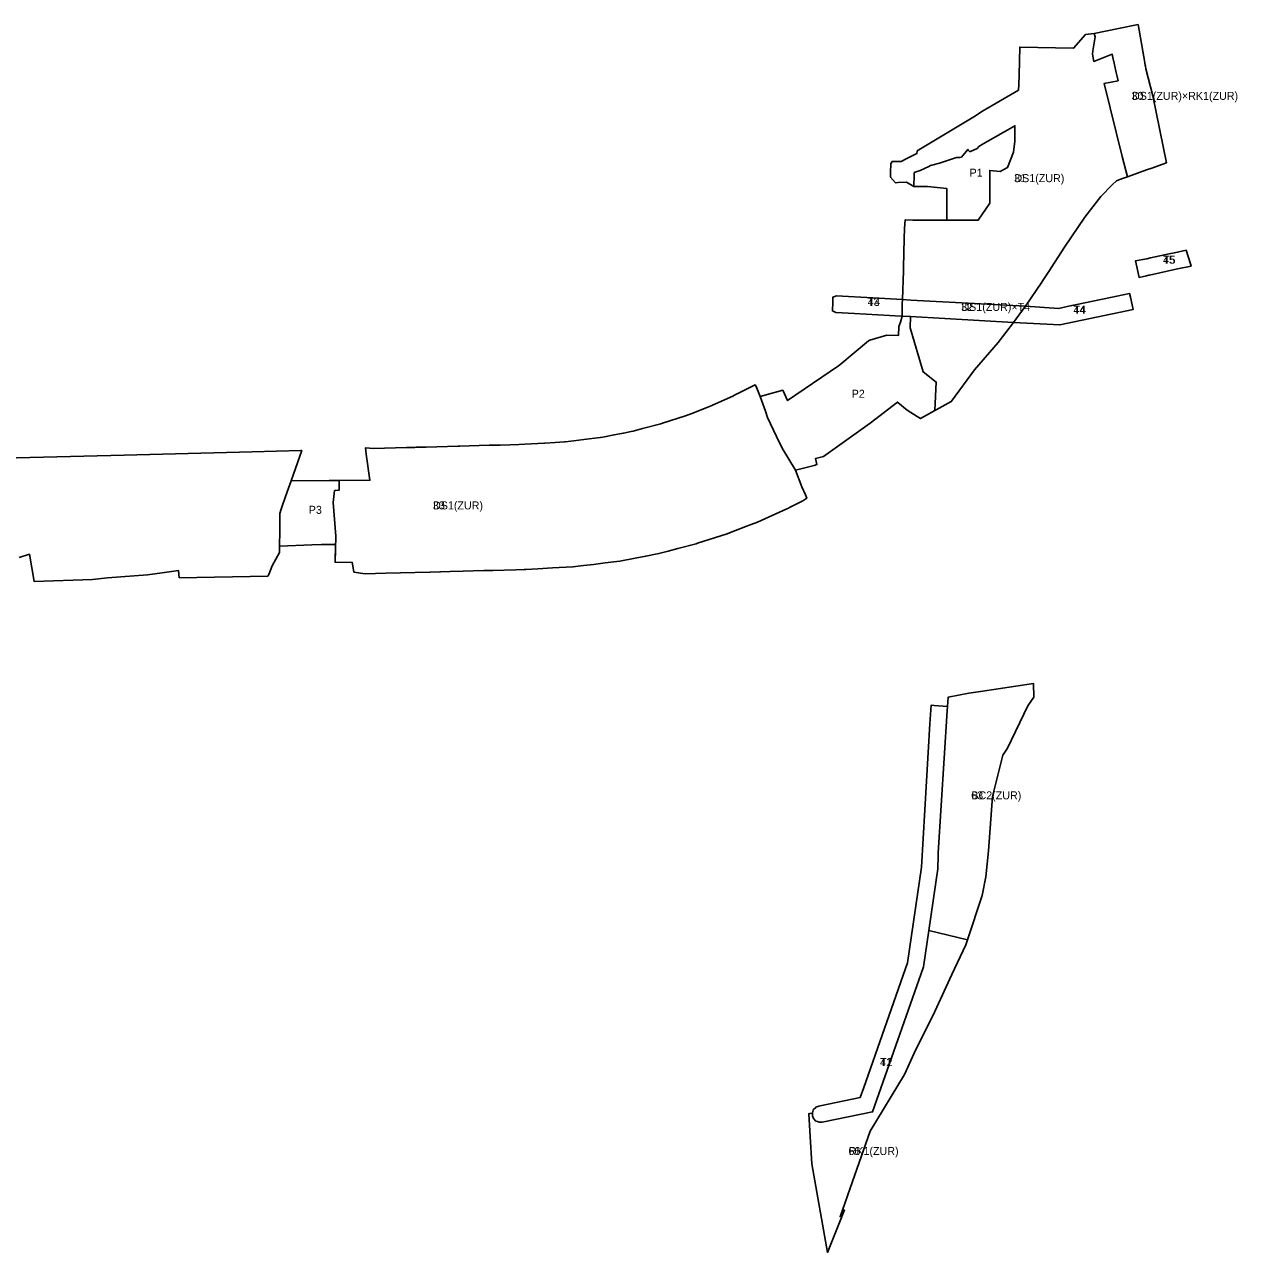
# Model space of a CAD drawing. Extents: x -501732 to -497651, y -1141409 to -1138069.
# Drawn here: x -498863 to -497651, y -1141409 to -1140182 of the extents above; entities that cross this region are included whole.
import ezdxf

# ---------------------------------------------------------------- set-up
doc = ezdxf.new("R2010")
doc.units = 0
for name, color, linetype in [('45', 7, 'Continuous'), ('51', 7, 'Continuous'), ('57', 7, 'Continuous'), ('59', 7, 'Continuous'), ('61', 7, 'Continuous'), ('62', 7, 'Continuous')]:
    doc.layers.add(name, color=color, linetype=linetype)

msp = doc.modelspace()

# ---------------------------------------------------------------- linework, layer by layer
at = {"layer": '45'}
for points in [[(-497873.51, -1140298.79), (-497874.77, -1140309.65), (-497880.89, -1140325.03), (-497888.02, -1140329.02), (-497898.51, -1140327.82), (-497898.53, -1140332.95), (-497898.6, -1140360.76), (-497910.06, -1140377.52), (-497914.148, -1140377.525), (-497941.564, -1140377.56), (-497941.57, -1140368.44), (-497941.52, -1140345.9), (-497960.94, -1140344.13), (-497972.87, -1140344.1), (-497974.54, -1140344.08), (-497974.21, -1140332.78), (-497974.13, -1140330.03), (-497967.99, -1140327.91), (-497959.454, -1140323.965), (-497957.69, -1140323.15), (-497956.48, -1140322.59), (-497948.98, -1140320.67), (-497931.93, -1140315.11), (-497928.49, -1140314.89), (-497926.91, -1140314.69), (-497920.36, -1140306.97), (-497920.1, -1140307.6), (-497918.69, -1140308.92), (-497917.76, -1140308.87), (-497911.33, -1140306.13), (-497909.39, -1140303.84), (-497905.09, -1140301.37), (-497882.9, -1140288.64), (-497873.46, -1140283.27), (-497873.49, -1140294.66)], [(-497977.812, -1140473.956), (-497978.1, -1140485.38), (-497965, -1140529.36), (-497952.03, -1140539.4), (-497953.325, -1140567.764), (-497967.87, -1140575.85), (-497971.23, -1140573.7), (-497981.02, -1140567.46), (-497990.31, -1140559.8), (-497990.749, -1140559.512), (-498018.24, -1140580.59), (-498064.77, -1140613.68), (-498072.91, -1140615.93), (-498071.35, -1140621.9), (-498074.25, -1140622.66), (-498092.81, -1140627.56), (-498106.12, -1140605.53), (-498111.793, -1140593.803), (-498120.9, -1140574.98), (-498122.87, -1140568.4), (-498128.1, -1140553.78), (-498105.46, -1140547.59), (-498100.702, -1140557.857), (-498049.646, -1140523.081), (-498048.385, -1140522.079), (-498019.752, -1140498.076), (-498018.382, -1140497.674), (-498001.33, -1140492.67), (-497989.83, -1140492.96), (-497989.6, -1140483.98), (-497987.8, -1140479.4), (-497986.174, -1140473.486)], [(-498596.956, -1140637.987), (-498558.761, -1140637.77), (-498549.008, -1140637.715), (-498549, -1140647.5), (-498553.57, -1140647.82), (-498554.94, -1140659.83), (-498552.29, -1140693.37), (-498553.06, -1140719.57), (-498552.643, -1140701.808), (-498559.063, -1140701.72), (-498566.41, -1140701.62), (-498576.28, -1140701.95), (-498608.546, -1140703.543), (-498608.24, -1140688.18), (-498608.2, -1140670.84), (-498606.99, -1140666.48), (-498605.42, -1140662.56), (-498600.801, -1140649.149)]]:
    msp.add_lwpolyline(points, close=True, dxfattribs=at)
at = {"layer": '51'}
for points in [[(-497750.361, -1140182.123), (-497744.65, -1140214.23), (-497744.34, -1140215.94), (-497743.12, -1140222.81), (-497742.97, -1140223.61), (-497742.46, -1140226.49), (-497735.58, -1140253.46), (-497722.038, -1140320.293), (-497733.802, -1140324.516), (-497736.638, -1140325.534), (-497741.761, -1140327.373), (-497757.255, -1140332.936), (-497760.746, -1140334.19), (-497766.22, -1140314.06), (-497784.27, -1140241.09), (-497770.35, -1140238.29), (-497771.3, -1140234.04), (-497772.19, -1140230.04), (-497773.87, -1140222.54), (-497774.27, -1140220.73), (-497775.52, -1140215.16), (-497776.29, -1140211.71), (-497794.66, -1140218.96), (-497796.02, -1140211.8), (-497795.48, -1140208.51), (-497793.18, -1140194.54), (-497794.171, -1140191.113), (-497769.85, -1140186.122)], [(-497793.18, -1140194.54), (-497795.48, -1140208.51), (-497796.02, -1140211.8), (-497794.66, -1140218.96), (-497776.29, -1140211.71), (-497775.52, -1140215.16), (-497774.27, -1140220.73), (-497773.87, -1140222.54), (-497772.19, -1140230.04), (-497771.3, -1140234.04), (-497770.35, -1140238.29), (-497784.27, -1140241.09), (-497766.22, -1140314.06), (-497760.746, -1140334.19), (-497765.849, -1140336.021), (-497768.534, -1140336.985), (-497771.924, -1140338.202), (-497776.305, -1140342.26), (-497787.404, -1140354.097), (-497803.679, -1140374.661), (-497823.893, -1140404.582), (-497840.21, -1140429.769), (-497845.516, -1140437.96), (-497846.62, -1140439.663), (-497862.96, -1140463.494), (-497977.396, -1140457.425), (-497985.937, -1140456.951), (-497984.944, -1140428.367), (-497984.83, -1140425.08), (-497984.067, -1140395.824), (-497983.81, -1140385.99), (-497983.185, -1140377.342), (-497975.381, -1140377.464), (-497957.21, -1140377.58), (-497941.564, -1140377.56), (-497941.57, -1140368.44), (-497941.52, -1140345.9), (-497960.94, -1140344.13), (-497972.87, -1140344.1), (-497974.54, -1140344.08), (-497981.91, -1140339.55), (-497990.299, -1140340.023), (-497992.965, -1140340.174), (-497997.64, -1140334.52), (-497997.649, -1140330.097), (-497997.617, -1140321.437), (-497997.053, -1140320.376), (-497996.942, -1140320.168), (-497996.24, -1140318.85), (-497987.3, -1140318.88), (-497981.4, -1140315.98), (-497971.33, -1140311.03), (-497971.26, -1140308.34), (-497912.788, -1140273.253), (-497906.46, -1140269.12), (-497869.75, -1140247.65), (-497869.596, -1140242.152), (-497869.32, -1140232.34), (-497868.54, -1140204.71), (-497814.724, -1140205.764), (-497803.04, -1140192.08), (-497794.171, -1140191.113)], [(-497742.025, -1140433.137), (-497749.305, -1140434.783), (-497752.954, -1140418.426), (-497745.487, -1140417.036), (-497741.556, -1140416.179), (-497738.052, -1140415.414), (-497719.331, -1140411.328), (-497714.01, -1140410.166), (-497702.315, -1140407.614), (-497697.93, -1140421.1), (-497697.403, -1140423.438), (-497710.808, -1140426.361), (-497738.975, -1140432.504), (-497739.599, -1140432.64)], [(-497757.956, -1140454.716), (-497755.151, -1140466.802), (-497828.392, -1140482.359), (-497841.639, -1140481.614), (-497874.808, -1140479.748), (-497863.221, -1140463.874), (-497862.96, -1140463.494), (-497829.666, -1140465.761), (-497821.285, -1140463.981), (-497777.943, -1140454.775), (-497758.85, -1140450.865)], [(-497985.937, -1140456.951), (-497986.07, -1140460.79), (-497986.174, -1140473.486), (-497987.181, -1140473.429), (-498033.913, -1140470.801), (-498052.607, -1140469.75), (-498055.788, -1140468.341), (-498055.53, -1140459.47), (-498055.484, -1140457.899), (-498055.384, -1140454.516), (-498051.68, -1140453.276), (-498015.461, -1140455.312)], [(-497863.221, -1140463.874), (-497874.808, -1140479.748), (-497977.812, -1140473.956), (-497986.174, -1140473.486), (-497986.07, -1140460.79), (-497985.937, -1140456.951), (-497977.396, -1140457.425), (-497862.96, -1140463.494)], [(-497940.79, -1140863.814), (-497941.059, -1140868.085), (-497950, -1141010), (-497950.085, -1141012.957), (-497950.453, -1141025.823), (-497959.442, -1141087.571), (-497964.714, -1141123.789), (-497965.056, -1141124.761), (-498015.675, -1141268.789), (-498064.477, -1141278.806), (-498066.144, -1141279.148), (-498069.236, -1141279.192), (-498070.925, -1141278.52), (-498072.345, -1141277.955), (-498074.707, -1141275.584), (-498075.885, -1141272.726), (-498075.895, -1141272.009), (-498075.921, -1141270.104), (-498075.928, -1141269.635), (-498074.954, -1141267.186), (-498074.691, -1141266.526), (-498072.598, -1141264.44), (-498072.32, -1141264.164), (-498069.462, -1141262.986), (-498068.179, -1141262.723), (-498028.144, -1141254.504), (-498024.601, -1141244.424), (-497980.812, -1141119.828), (-497966.901, -1141024.267), (-497958.345, -1140881.029), (-497957.238, -1140862.504), (-497954.3, -1140862.62)]]:
    msp.add_lwpolyline(points, close=True, dxfattribs=at)
msp.add_lwpolyline([(-498911.97, -1140616.22), (-498763.779, -1140612.414), (-498635.836, -1140608.996), (-498587.232, -1140607.698), (-498586.309, -1140607.658), (-498594.68, -1140631.38), (-498596.956, -1140637.987), (-498558.761, -1140637.77), (-498549.008, -1140637.715), (-498518.24, -1140637.54), (-498521.824, -1140611.416), (-498522.66, -1140605.32), (-498514.662, -1140605.76), (-498481.482, -1140604.874), (-498479.827, -1140604.83), (-498473.333, -1140604.656), (-498471.913, -1140604.618), (-498462.065, -1140604.355), (-498440.64, -1140603.783), (-498430.138, -1140603.502), (-498428.221, -1140603.451), (-498419.006, -1140603.196), (-498398.992, -1140602.641), (-498387.928, -1140602.335), (-498377.939, -1140602.058), (-498369.099, -1140601.813), (-498363.353, -1140601.491), (-498343.694, -1140600.388), (-498343.303, -1140600.366), (-498333.112, -1140599.794), (-498323.736, -1140599.268), (-498323.104, -1140599.19), (-498314.182, -1140598.086), (-498304.366, -1140596.872), (-498287.957, -1140594.843), (-498285.35, -1140594.337), (-498274.137, -1140592.159), (-498264.802, -1140590.346), (-498257.129, -1140588.856), (-498255.131, -1140588.333), (-498245.571, -1140585.832), (-498227.312, -1140581.055), (-498225.57, -1140580.489), (-498202.84, -1140573.11), (-498196.526, -1140570.684), (-498180.452, -1140564.508), (-498178.766, -1140563.86), (-498155.285, -1140553.385), (-498151.261, -1140551.331), (-498150.408, -1140550.895), (-498137.212, -1140544.157), (-498133.079, -1140542.247), (-498132.18, -1140543.96), (-498128.1, -1140553.78), (-498105.46, -1140547.59), (-498100.702, -1140557.857), (-498049.646, -1140523.081), (-498048.385, -1140522.079), (-498019.752, -1140498.076), (-498018.382, -1140497.674), (-498001.33, -1140492.67), (-497989.83, -1140492.96), (-497989.6, -1140483.98), (-497987.8, -1140479.4), (-497986.174, -1140473.486), (-497977.812, -1140473.956), (-497874.808, -1140479.748), (-497890.3, -1140499.996), (-497913.717, -1140527.13), (-497936.936, -1140558.427), (-497936.83, -1140558.56), (-497936.62, -1140558.714), (-497937.22, -1140558.81), (-497967.87, -1140575.85), (-497971.23, -1140573.7), (-497981.02, -1140567.46), (-497990.31, -1140559.8), (-497990.749, -1140559.512), (-498018.24, -1140580.59), (-498064.77, -1140613.68), (-498072.91, -1140615.93), (-498071.35, -1140621.9), (-498074.25, -1140622.66), (-498092.81, -1140627.56), (-498086.34, -1140644.21), (-498082.67, -1140652.13), (-498081.436, -1140655.582), (-498085.369, -1140658.038), (-498098.651, -1140664.82), (-498099.854, -1140665.434), (-498101.363, -1140666.204), (-498130.852, -1140679.36), (-498140.654, -1140683.126), (-498158.761, -1140690.084), (-498161.095, -1140690.981), (-498190.601, -1140700.559), (-498192.164, -1140701.066), (-498210.389, -1140705.834), (-498219.943, -1140708.334), (-498229.365, -1140710.799), (-498231.078, -1140711.132), (-498242.417, -1140713.334), (-498252.872, -1140715.365), (-498268.347, -1140718.37), (-498274.437, -1140719.123), (-498283.056, -1140720.189), (-498294.735, -1140721.634), (-498304.746, -1140722.872), (-498312.551, -1140723.837), (-498315.16, -1140723.983), (-498315.351, -1140723.994), (-498335.52, -1140725.126), (-498335.576, -1140725.129), (-498350.18, -1140725.948), (-498362.193, -1140726.622), (-498363.866, -1140726.716), (-498372.437, -1140726.953), (-498395.246, -1140727.586), (-498404.381, -1140727.839), (-498415.103, -1140728.136), (-498424.822, -1140728.405), (-498438.021, -1140728.758), (-498447.686, -1140729.016), (-498448.223, -1140729.03), (-498457.932, -1140729.289), (-498458.141, -1140729.295), (-498502.393, -1140730.477), (-498522.815, -1140731.022), (-498534.089, -1140729.416), (-498535.16, -1140723.08), (-498535.79, -1140719.63), (-498553.06, -1140719.57), (-498552.643, -1140701.808), (-498559.063, -1140701.72), (-498566.41, -1140701.62), (-498576.28, -1140701.95), (-498608.546, -1140703.543), (-498608.67, -1140709.77), (-498616.02, -1140723.18), (-498619.06, -1140731.91), (-498620.29, -1140733.478), (-498708.816, -1140735.001), (-498709.65, -1140727.63), (-498725.72, -1140729.92), (-498740.49, -1140732.02), (-498780.63, -1140734.94), (-498795.52, -1140736.85), (-498853.837, -1140738.595), (-498858.59, -1140711.59), (-498868.78, -1140714.9)], dxfattribs=at)
at = {"layer": '57'}
for points in [[(-497750.361, -1140182.123), (-497744.65, -1140214.23), (-497744.34, -1140215.94), (-497743.12, -1140222.81), (-497742.97, -1140223.61), (-497742.46, -1140226.49), (-497735.58, -1140253.46), (-497722.038, -1140320.293), (-497733.802, -1140324.516), (-497736.638, -1140325.534), (-497741.761, -1140327.373), (-497757.255, -1140332.936), (-497760.746, -1140334.19), (-497766.22, -1140314.06), (-497784.27, -1140241.09), (-497770.35, -1140238.29), (-497771.3, -1140234.04), (-497772.19, -1140230.04), (-497773.87, -1140222.54), (-497774.27, -1140220.73), (-497775.52, -1140215.16), (-497776.29, -1140211.71), (-497794.66, -1140218.96), (-497796.02, -1140211.8), (-497795.48, -1140208.51), (-497793.18, -1140194.54), (-497794.171, -1140191.113), (-497769.85, -1140186.122)], [(-497906.09, -1141052.54), (-497920.923, -1141096.824), (-497959.442, -1141087.571), (-497950.453, -1141025.823), (-497950.085, -1141012.957), (-497950, -1141010), (-497941.059, -1140868.085), (-497940.79, -1140863.814), (-497940.12, -1140854.25), (-497919.46, -1140850.42), (-497907.84, -1140848.72), (-497854.86, -1140840.55), (-497854.48, -1140854.34), (-497860.49, -1140863.16), (-497880.69, -1140905.18), (-497885.67, -1140912.21), (-497895.94, -1140953.5), (-497899.9, -1141008.04), (-497902.6, -1141034.05)], [(-497920.923, -1141096.824), (-497922.56, -1141101.71), (-497936.6, -1141131.47), (-497953.58, -1141168.63), (-497974.01, -1141210.14), (-497983.96, -1141231.47), (-498018.11, -1141287.98), (-498035.73, -1141338.3), (-498048.14, -1141373.58), (-498043.93, -1141366.76), (-498048.79, -1141379.42), (-498060.66, -1141409.3), (-498076.29, -1141320.9), (-498078.06, -1141293.56), (-498079.54, -1141270.72), (-498078.55, -1141270.48), (-498075.921, -1141270.104), (-498075.895, -1141272.009), (-498075.885, -1141272.726), (-498074.707, -1141275.584), (-498072.345, -1141277.955), (-498070.925, -1141278.52), (-498069.236, -1141279.192), (-498066.144, -1141279.148), (-498064.477, -1141278.806), (-498015.675, -1141268.789), (-497965.056, -1141124.761), (-497964.714, -1141123.789), (-497959.442, -1141087.571)]]:
    msp.add_lwpolyline(points, close=True, dxfattribs=at)
at = {"layer": '59'}
msp.add_lwpolyline([(-498911.97, -1140616.22), (-498763.779, -1140612.414), (-498635.836, -1140608.996), (-498587.232, -1140607.698), (-498586.309, -1140607.658), (-498594.68, -1140631.38), (-498596.956, -1140637.987), (-498558.761, -1140637.77), (-498549.008, -1140637.715), (-498518.24, -1140637.54), (-498521.824, -1140611.416), (-498522.66, -1140605.32), (-498514.662, -1140605.76), (-498481.482, -1140604.874), (-498479.827, -1140604.83), (-498473.333, -1140604.656), (-498471.913, -1140604.618), (-498462.065, -1140604.355), (-498440.64, -1140603.783), (-498430.138, -1140603.502), (-498428.221, -1140603.451), (-498419.006, -1140603.196), (-498398.992, -1140602.641), (-498387.928, -1140602.335), (-498377.939, -1140602.058), (-498369.099, -1140601.813), (-498363.353, -1140601.491), (-498343.694, -1140600.388), (-498343.303, -1140600.366), (-498333.112, -1140599.794), (-498323.736, -1140599.268), (-498323.104, -1140599.19), (-498314.182, -1140598.086), (-498304.366, -1140596.872), (-498287.957, -1140594.843), (-498285.35, -1140594.337), (-498274.137, -1140592.159), (-498264.802, -1140590.346), (-498257.129, -1140588.856), (-498255.131, -1140588.333), (-498245.571, -1140585.832), (-498227.312, -1140581.055), (-498225.57, -1140580.489), (-498202.84, -1140573.11), (-498196.526, -1140570.684), (-498180.452, -1140564.508), (-498178.766, -1140563.86), (-498155.285, -1140553.385), (-498151.261, -1140551.331), (-498150.408, -1140550.895), (-498137.212, -1140544.157), (-498133.079, -1140542.247), (-498132.18, -1140543.96), (-498128.1, -1140553.78), (-498105.46, -1140547.59), (-498100.702, -1140557.857), (-498049.646, -1140523.081), (-498048.385, -1140522.079), (-498019.752, -1140498.076), (-498018.382, -1140497.674), (-498001.33, -1140492.67), (-497989.83, -1140492.96), (-497989.6, -1140483.98), (-497987.8, -1140479.4), (-497986.174, -1140473.486), (-497987.181, -1140473.429), (-498033.913, -1140470.801), (-498052.607, -1140469.75), (-498055.788, -1140468.341), (-498055.53, -1140459.47), (-498055.484, -1140457.899), (-498055.384, -1140454.516), (-498051.68, -1140453.276), (-498015.461, -1140455.312), (-497985.937, -1140456.951), (-497984.944, -1140428.367), (-497984.83, -1140425.08), (-497984.067, -1140395.824), (-497983.81, -1140385.99), (-497983.185, -1140377.342), (-497975.381, -1140377.464), (-497957.21, -1140377.58), (-497941.564, -1140377.56), (-497941.57, -1140368.44), (-497941.52, -1140345.9), (-497960.94, -1140344.13), (-497972.87, -1140344.1), (-497974.54, -1140344.08), (-497981.91, -1140339.55), (-497990.299, -1140340.023), (-497992.965, -1140340.174), (-497997.64, -1140334.52), (-497997.649, -1140330.097), (-497997.617, -1140321.437), (-497997.053, -1140320.376), (-497996.942, -1140320.168), (-497996.24, -1140318.85), (-497987.3, -1140318.88), (-497981.4, -1140315.98), (-497971.33, -1140311.03), (-497971.26, -1140308.34), (-497912.788, -1140273.253), (-497906.46, -1140269.12), (-497869.75, -1140247.65), (-497869.596, -1140242.152), (-497869.32, -1140232.34), (-497868.54, -1140204.71), (-497814.724, -1140205.764), (-497803.04, -1140192.08), (-497794.171, -1140191.113), (-497769.85, -1140186.122), (-497750.361, -1140182.123), (-497744.65, -1140214.23), (-497744.34, -1140215.94), (-497743.12, -1140222.81), (-497742.97, -1140223.61), (-497742.46, -1140226.49), (-497735.58, -1140253.46), (-497722.038, -1140320.293), (-497733.802, -1140324.516), (-497736.638, -1140325.534), (-497741.761, -1140327.373), (-497757.255, -1140332.936), (-497760.746, -1140334.19), (-497765.849, -1140336.021), (-497768.534, -1140336.985), (-497771.924, -1140338.202), (-497776.305, -1140342.26), (-497787.404, -1140354.097), (-497803.679, -1140374.661), (-497823.893, -1140404.582), (-497840.21, -1140429.769), (-497845.516, -1140437.96), (-497846.62, -1140439.663), (-497862.96, -1140463.494), (-497829.666, -1140465.761), (-497821.285, -1140463.981), (-497777.943, -1140454.775), (-497758.85, -1140450.865), (-497757.956, -1140454.716), (-497755.151, -1140466.802), (-497828.392, -1140482.359), (-497841.639, -1140481.614), (-497874.808, -1140479.748), (-497890.3, -1140499.996), (-497913.717, -1140527.13), (-497936.936, -1140558.427), (-497936.83, -1140558.56), (-497936.62, -1140558.714), (-497937.22, -1140558.81), (-497967.87, -1140575.85), (-497971.23, -1140573.7), (-497981.02, -1140567.46), (-497990.31, -1140559.8), (-497990.749, -1140559.512), (-498018.24, -1140580.59), (-498064.77, -1140613.68), (-498072.91, -1140615.93), (-498071.35, -1140621.9), (-498074.25, -1140622.66), (-498092.81, -1140627.56), (-498086.34, -1140644.21), (-498082.67, -1140652.13), (-498081.436, -1140655.582), (-498085.369, -1140658.038), (-498098.651, -1140664.82), (-498099.854, -1140665.434), (-498101.363, -1140666.204), (-498130.852, -1140679.36), (-498140.654, -1140683.126), (-498158.761, -1140690.084), (-498161.095, -1140690.981), (-498190.601, -1140700.559), (-498192.164, -1140701.066), (-498210.389, -1140705.834), (-498219.943, -1140708.334), (-498229.365, -1140710.799), (-498231.078, -1140711.132), (-498242.417, -1140713.334), (-498252.872, -1140715.365), (-498268.347, -1140718.37), (-498274.437, -1140719.123), (-498283.056, -1140720.189), (-498294.735, -1140721.634), (-498304.746, -1140722.872), (-498312.551, -1140723.837), (-498315.16, -1140723.983), (-498315.351, -1140723.994), (-498335.52, -1140725.126), (-498335.576, -1140725.129), (-498350.18, -1140725.948), (-498362.193, -1140726.622), (-498363.866, -1140726.716), (-498372.437, -1140726.953), (-498395.246, -1140727.586), (-498404.381, -1140727.839), (-498415.103, -1140728.136), (-498424.822, -1140728.405), (-498438.021, -1140728.758), (-498447.686, -1140729.016), (-498448.223, -1140729.03), (-498457.932, -1140729.289), (-498458.141, -1140729.295), (-498502.393, -1140730.477), (-498522.815, -1140731.022), (-498534.089, -1140729.416), (-498535.16, -1140723.08), (-498535.79, -1140719.63), (-498553.06, -1140719.57), (-498552.643, -1140701.808), (-498559.063, -1140701.72), (-498566.41, -1140701.62), (-498576.28, -1140701.95), (-498608.546, -1140703.543), (-498608.67, -1140709.77), (-498616.02, -1140723.18), (-498619.06, -1140731.91), (-498620.29, -1140733.478), (-498708.816, -1140735.001), (-498709.65, -1140727.63), (-498725.72, -1140729.92), (-498740.49, -1140732.02), (-498780.63, -1140734.94), (-498795.52, -1140736.85), (-498853.837, -1140738.595), (-498858.59, -1140711.59), (-498868.78, -1140714.9)], dxfattribs=at)
for points in [[(-497742.025, -1140433.137), (-497749.305, -1140434.783), (-497752.954, -1140418.426), (-497745.487, -1140417.036), (-497741.556, -1140416.179), (-497738.052, -1140415.414), (-497719.331, -1140411.328), (-497714.01, -1140410.166), (-497702.315, -1140407.614), (-497697.93, -1140421.1), (-497697.403, -1140423.438), (-497710.808, -1140426.361), (-497738.975, -1140432.504), (-497739.599, -1140432.64)], [(-497860.49, -1140863.16), (-497880.69, -1140905.18), (-497885.67, -1140912.21), (-497895.94, -1140953.5), (-497899.9, -1141008.04), (-497902.6, -1141034.05), (-497906.09, -1141052.54), (-497920.923, -1141096.824), (-497922.56, -1141101.71), (-497936.6, -1141131.47), (-497953.58, -1141168.63), (-497974.01, -1141210.14), (-497983.96, -1141231.47), (-498018.11, -1141287.98), (-498035.73, -1141338.3), (-498048.14, -1141373.58), (-498043.93, -1141366.76), (-498048.79, -1141379.42), (-498060.66, -1141409.3), (-498076.29, -1141320.9), (-498078.06, -1141293.56), (-498079.54, -1141270.72), (-498078.55, -1141270.48), (-498075.921, -1141270.104), (-498075.928, -1141269.635), (-498074.954, -1141267.186), (-498074.691, -1141266.526), (-498072.598, -1141264.44), (-498072.32, -1141264.164), (-498069.462, -1141262.986), (-498068.179, -1141262.723), (-498028.144, -1141254.504), (-498024.601, -1141244.424), (-497980.812, -1141119.828), (-497966.901, -1141024.267), (-497958.345, -1140881.029), (-497957.238, -1140862.504), (-497954.3, -1140862.62), (-497940.79, -1140863.814), (-497940.12, -1140854.25), (-497919.46, -1140850.42), (-497907.84, -1140848.72), (-497854.86, -1140840.55), (-497854.48, -1140854.34)]]:
    msp.add_lwpolyline(points, close=True, dxfattribs=at)

# ---------------------------------------------------------------- texts
at = {"layer": '45'}
for s, p in [('P1', (-497918.742, -1140334.177)), ('P2', (-498036.613, -1140555.1)), ('P3', (-498579.282, -1140671.107))]:
    msp.add_text(s, height=8, dxfattribs=at).set_placement(p)
at = {"layer": '51'}
for s, p in [('DS1(ZUR)×RK1(ZUR)', (-497756.422, -1140257.362)), ('DS1(ZUR)', (-497873.954, -1140339.638)), ('T5', (-497725.381, -1140421.134)), ('T4', (-498020.628, -1140463.284)), ('DS1(ZUR)×T4', (-497926.883, -1140468.296)), ('T4', (-497814.912, -1140471.07)), ('DS1(ZUR)', (-498455.077, -1140666.691)), ('T2', (-498008.291, -1141223.085))]:
    msp.add_text(s, height=8, dxfattribs=at).set_placement(p)
at = {"layer": '57'}
for s, p in [('DS1(ZUR)×RK1(ZUR)', (-497756.422, -1140257.362)), ('BC2(ZUR)', (-497916.969, -1140956.458)), ('RK1(ZUR)', (-498039.639, -1141311.931))]:
    msp.add_text(s, height=8, dxfattribs=at).set_placement(p)
at = {"layer": '61'}
for s, p in [('30', (-497756.869, -1140257.362)), ('31', (-497874.133, -1140339.638)), ('45', (-497725.381, -1140421.134)), ('43', (-498020.628, -1140463.284)), ('32', (-497927.152, -1140468.296)), ('44', (-497814.912, -1140471.07)), ('33', (-498455.256, -1140666.691)), ('41', (-498008.291, -1141223.085))]:
    msp.add_text(s, height=8, dxfattribs=at).set_placement(p)
at = {"layer": '62'}
for s, p in [('30', (-497756.869, -1140257.362)), ('63', (-497917.148, -1140956.458)), ('66', (-498039.818, -1141311.931))]:
    msp.add_text(s, height=8, dxfattribs=at).set_placement(p)

doc.saveas('drawing.dxf')
